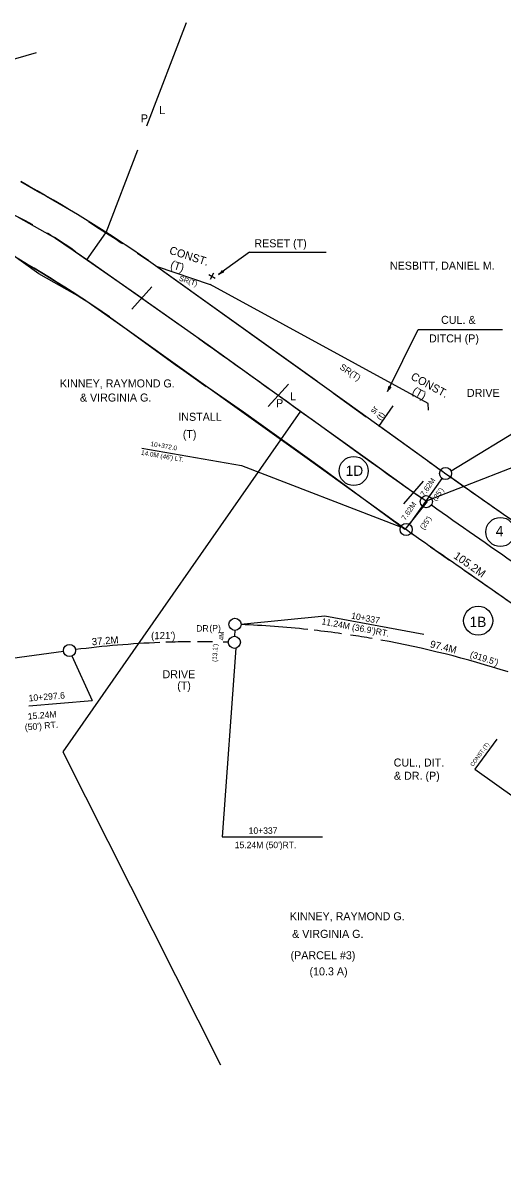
# Model space of a CAD drawing. Extents: x 624 to 1448, y 1599 to 1865.
# Drawn here: x 1147.3 to 1254.2, y 1600.9 to 1857.1 of the extents above; entities that cross this region are included whole.
import ezdxf

# ---------------------------------------------------------------- set-up
doc = ezdxf.new("R2010")
doc.units = 0
for name, color, linetype in [('C_I', 7, 'Continuous'), ('C_TIC', 7, 'Continuous'), ('CPSM', 7, 'Continuous'), ('L_A', 7, 'Continuous'), ('L_C', 7, 'Continuous'), ('L_I', 7, 'Continuous'), ('Level 16', 7, 'Continuous'), ('Level 30', 7, 'Continuous'), ('Level 60', 7, 'Continuous'), ('ODIML_P', 7, 'Continuous')]:
    doc.layers.add(name, color=color, linetype=linetype)

msp = doc.modelspace()

# ---------------------------------------------------------------- linework, layer by layer
at = {"layer": 'C_I'}
for p, q in [((1143.46, 1848.56), (1150.35, 1850.6)), ((1197.77, 1806.11), (1190.88, 1801.09)), ((1197.77, 1806.11), (1214.81, 1806.11)), ((1188.67, 1801.12), (1190.07, 1800.3)), ((1189.75, 1801.38), (1188.99, 1800.01)), ((1228.5, 1775.03), (1235.33, 1788.84)), ((1235.33, 1788.84), (1254.06, 1788.84)), ((1226.51, 1767.27), (1229.73, 1771.85)), ((1252.79, 1697.62), (1247.89, 1690.87)), ((1247.89, 1690.87), (1257.19, 1684.28))]:
    msp.add_line(p, q, dxfattribs=at)
at = {"layer": 'C_TIC'}
for p, q in [((1194.47, 1721.9), (1194.42, 1720.55)), ((1119.66, 1712.21), (1156.34, 1717.18))]:
    msp.add_line(p, q, dxfattribs=at)
for centre, radius, start, end in [((1186.82, 1499.54), 223.76, 83.8659, 87.6946), ((1186.82, 1499.54), 223.76, 81.9273, 83.5023), ((1186.82, 1499.54), 219.76, 90.5767, 91.9984), ((1186.82, 1499.54), 219.76, 89.2914, 90.1765), ((1185.68, 1499.56), 219.76, 88.0891, 88.3832), ((1186.82, 1499.54), 223.76, 80.1531, 81.412), ((1186.82, 1499.54), 223.76, 72.1716, 79.6486), ((1186.82, 1499.54), 219.76, 92.3655, 97.2601)]:
    msp.add_arc(centre, radius, start, end, dxfattribs=at)
at = {"layer": 'CPSM'}
msp.add_line((1342.48, 1791.88), (1237.06, 1750.6), dxfattribs=at)
at = {"layer": 'L_A'}
msp.add_lwpolyline([(1146.28, 1813.9), (1154.59, 1809.17), (1162.17, 1803.99), (1188.52, 1785.46), (1210.43, 1769.73), (1224.02, 1759.93), (1233.89, 1752.85), (1237.31, 1750.56), (1232.37, 1744.32), (1213.97, 1757.79), (1196.41, 1770.43), (1181.23, 1780.96), (1170.26, 1788.9), (1160.59, 1795.77), (1150.85, 1801.23), (1144.54, 1805.75)], dxfattribs=at)
at = {"layer": 'L_C'}
for p, q in [((1242.65, 1757.37), (1310.72, 1798.99)), ((1173.78, 1762.38), (1195.97, 1758.57)), ((1195.97, 1758.57), (1231.37, 1744.86))]:
    msp.add_line(p, q, dxfattribs=at)
for centre in [(1220.95, 1757.33), (1253.6, 1743.74), (1248.67, 1723.98)]:
    msp.add_circle(centre, 3.24, dxfattribs=at)
at = {"layer": 'L_I'}
for p, q in [((1183.62, 1857.14), (1174.84, 1834.12)), ((1172.83, 1828.83), (1165.8, 1810.41)), ((1161.54, 1804.41), (1165.8, 1810.41)), ((1159.03, 1806.19), (1174.09, 1795.65)), ((1173.78, 1795.87), (1182.3, 1789.8)), ((1209.12, 1770.66), (1156.17, 1694.8)), ((1233.4, 1745.4), (1240.63, 1755.67)), ((1195.84, 1723.22), (1214.52, 1725.06)), ((1214.52, 1725.06), (1236.55, 1720.96)), ((1194.73, 1717.88), (1191.7, 1675.82)), ((1158.23, 1716.16), (1162.72, 1706.21)), ((1148.65, 1705.04), (1162.72, 1706.21)), ((1156.17, 1694.8), (1191.31, 1625.06)), ((1191.7, 1675.82), (1213.99, 1675.82))]:
    msp.add_line(p, q, dxfattribs=at)
for centre in [(1241.41, 1756.77), (1237.12, 1750.5), (1232.62, 1744.3), (1194.52, 1723.17), (1194.38, 1719.17), (1157.66, 1717.35)]:
    msp.add_circle(centre, 1.35, dxfattribs=at)
for start, end in [(61.0375, 77.7037), (54.5772, 58.8831)]:
    msp.add_arc((1101.07, 1724.7), 100, start, end, dxfattribs=at)
for points in [[(1186.37, 1786.9), (1204.16, 1774.21), (1234.31, 1752.55), (1236.02, 1751.34)], [(1238.24, 1749.77), (1257.42, 1736.33), (1273.09, 1725.39)]]:
    msp.add_spline(points, degree=3, dxfattribs=at)
at = {"layer": 'Level 16'}
for p, q in [((1191.71, 1801.86), (1191.6, 1801.68)), ((1191.87, 1801.64), (1191.66, 1801.6)), ((1191.75, 1802), (1191.81, 1801.76)), ((1192.02, 1801.63), (1191.8, 1801.76)), ((1228.83, 1776.24), (1228.99, 1776.05)), ((1228.87, 1776.09), (1228.86, 1775.88)), ((1229.1, 1775.98), (1228.94, 1775.84)), ((1229.24, 1776.04), (1228.99, 1776.05))]:
    msp.add_line(p, q, dxfattribs=at)
for centre, start, end in [((1188.87, 1803.86), 306.0701, 327.2934), ((1192.9, 1798.33), 104.8731, 126.0963), ((1225.42, 1776.5), 334.3662, 355.5894), ((1231.58, 1773.55), 133.1691, 154.3924)]:
    msp.add_arc(centre, 3.42, start, end, dxfattribs=at)
at = {"layer": 'Level 30'}
for p, q in [((1237.55, 1772.39), (1188.98, 1798.88)), ((1237.64, 1770.88), (1237.55, 1772.39))]:
    msp.add_line(p, q, dxfattribs=at)
msp.add_lwpolyline([(1176.99, 1802.96), (1188.98, 1798.88)], dxfattribs=at)
at = {"layer": 'Level 60'}
for p, q in [((1171.57, 1793.36), (1175.98, 1798.38)), ((1201.89, 1771.73), (1206.43, 1776.7)), ((1232.09, 1750.02), (1236.52, 1755.09))]:
    msp.add_line(p, q, dxfattribs=at)
at = {"layer": 'ODIML_P'}
for p, q in [((1219.45, 1772.59), (1237.38, 1759.66)), ((1210.59, 1760.2), (1228.64, 1747.17))]:
    msp.add_line(p, q, dxfattribs=at)
for points in [[(1146.82, 1821.82), (1148.25, 1821.02), (1149.68, 1820.22), (1151.1, 1819.41), (1152.52, 1818.59), (1153.94, 1817.77), (1155.35, 1816.94), (1156.76, 1816.1), (1158.01, 1815.36)], [(1161.9, 1812.88), (1162.32, 1812.62), (1163.7, 1811.75), (1165.09, 1810.87), (1166.47, 1809.98), (1167.84, 1809.09), (1169.21, 1808.19), (1169.47, 1808.03)], [(1146.41, 1804.52), (1147.79, 1803.71), (1149.16, 1802.89), (1150.54, 1802.06), (1151.9, 1801.23), (1153.27, 1800.39), (1154.63, 1799.54), (1155.98, 1798.69), (1157.33, 1797.83), (1158.68, 1796.96), (1160.02, 1796.09), (1161.36, 1795.21), (1162.69, 1794.32), (1164.02, 1793.43), (1165.35, 1792.53), (1166.59, 1791.67), (1166.38, 1791.82), (1177.08, 1784.17)], [(1172.8, 1805.88), (1173.34, 1805.52), (1174.69, 1804.59), (1175.24, 1804.22), (1175.24, 1804.22), (1212.71, 1777.41)], [(1175.24, 1804.22), (1219.45, 1772.59)], [(1166.38, 1791.82), (1210.59, 1760.2)], [(1180.79, 1781.42), (1188.1, 1776.19)], [(1191.37, 1773.94), (1210.59, 1760.2), (1228.64, 1747.17), (1228.65, 1747.17), (1229.73, 1746.39), (1230.55, 1745.8), (1231.53, 1745.1)], [(1216.42, 1774.66), (1219.41, 1772.53), (1223.72, 1769.42)], [(1226.98, 1767.16), (1237.38, 1759.66), (1237.38, 1759.65), (1238.49, 1758.85), (1240.31, 1757.55)], [(1242.51, 1756), (1248.06, 1752.11), (1254.3, 1747.74), (1260.54, 1743.37), (1266.78, 1739), (1269.31, 1737.23)], [(1233.73, 1743.53), (1235.14, 1742.53)], [(1238.02, 1740.45), (1239.24, 1739.6), (1242.28, 1737.47)], [(1245.57, 1735.26), (1251.8, 1730.9), (1258.05, 1726.53), (1264.29, 1722.16), (1270.53, 1717.79), (1271.9, 1716.83), (1273.28, 1715.86), (1278.14, 1712.45), (1283.01, 1709.04), (1285.73, 1707.14)]]:
    msp.add_lwpolyline(points, dxfattribs=at)
for radius in [335.89, 320.65]:
    msp.add_arc((984.41, 1527.8), radius, 55.3797, 61.0858, dxfattribs=at)
for points in [[(1237.38, 1759.65), (1241.82, 1756.48), (1254.3, 1747.74), (1266.78, 1739), (1279.27, 1730.26), (1282.01, 1728.34), (1291.75, 1721.52), (1304.23, 1712.78), (1316.72, 1704.04), (1329.16, 1695.32), (1341.82, 1686.83), (1354.38, 1678.04), (1366.69, 1669.05), (1379.22, 1660.23), (1391.46, 1650.9), (1403.62, 1641.59), (1415.8, 1632.22), (1427.84, 1622.54), (1439.44, 1612.4)], [(1228.65, 1747.17), (1233, 1744.06), (1245.56, 1735.27), (1258.05, 1726.53), (1270.53, 1717.79), (1273.28, 1715.86), (1283.01, 1709.04), (1295.5, 1700.3), (1307.98, 1691.56), (1320.55, 1682.76), (1333.21, 1674.27), (1345.52, 1665.65), (1357.82, 1656.67), (1370.21, 1647.94), (1382.21, 1638.79), (1394.35, 1629.5), (1406.38, 1620.25), (1418.05, 1610.87), (1429.41, 1600.93)]]:
    msp.add_spline(points, degree=3, dxfattribs=at)

# ---------------------------------------------------------------- texts
at = {"layer": 'C_I'}
for s, height, p in [('RESET (T)', 1.783, (1198.84, 1807.17)), ('CUL. &', 1.783, (1240.41, 1790.11)), ('DITCH (P)', 1.783, (1237.71, 1785.98)), ('DRIVE', 1.783, (1246.16, 1773.84)), ('INSTALL', 1.783, (1181.9, 1768.51)), ('(T)', 1.783, (1182.9, 1764.65)), ('DR', 1.426, (1185.9, 1721.56)), ('(P)', 1.426, (1188.83, 1721.63)), ('DRIVE', 1.783, (1178.38, 1711.16)), ('(T)', 1.783, (1181.65, 1708.63)), ('CUL., DIT. ', 1.783, (1229.84, 1691.49)), ('& DR. (P)', 1.783, (1229.91, 1688.55))]:
    msp.add_text(s, height=height, dxfattribs=at).set_placement(p)
for s, height, rotation, p in [('CONST.', 1.783, 342.1843, (1179.75, 1805.76)), ('(T)', 1.783, 342.1843, (1179.98, 1802.61)), ('SR(T)', 1.141, 341.1277, (1181.97, 1799.8)), ('SR(T)', 1.426, 326.5512, (1217.7, 1780.14)), ('CONST.', 1.783, 331.5584, (1233.49, 1777.84)), ('(T)', 1.783, 331.5584, (1233.81, 1774.63)), ('sr', 1.4, 54.8664, (1225.59, 1769.95)), ('(t)', 1.4, 54.8664, (1227.01, 1768.44)), ('7.62M', 1.17, 55.1084, (1236.64, 1751.58)), ("(25')", 1.17, 55.1084, (1239.28, 1750.51)), ('7.62M', 1.17, 55.1084, (1232.42, 1746.24)), ("(25')", 1.17, 55.1084, (1236.53, 1744.15)), ('105.2M', 1.783, 324.915, (1243.02, 1738.05)), ('37.2M', 1.605, 4.5423, (1162.7, 1718.49)), ("(121')", 1.605, 0.5423, (1175.84, 1719.85)), ('4M', 1.04, 87.3955, (1191.99, 1719.57)), ('97.4M', 1.605, 346.3199, (1237.84, 1718.06)), ("(13.1')", 1.04, 87.3955, (1190.49, 1714.78)), ("(319.5')", 1.444, 342.3199, (1246.73, 1715.89)), ('CONST.(T)', 0.891, 54.0302, (1247.53, 1691.41))]:
    msp.add_text(s, height=height, rotation=rotation, dxfattribs=at).set_placement(p)
at = {"layer": 'L_A'}
for s, p in [('NESBITT, DANIEL M.', (1229.02, 1802.19)), ('KINNEY, RAYMOND G.', (1155.54, 1775.95)), ('& VIRGINIA G.', (1159.99, 1772.8)), ('KINNEY, RAYMOND G.', (1206.73, 1657.24)), ('& VIRGINIA G.', (1207.23, 1653.32)), ('(PARCEL #3)', (1206.89, 1648.55)), ('(10.3 A)', (1211.11, 1644.96))]:
    msp.add_text(s, height=1.783, dxfattribs=at).set_placement(p)
at = {"layer": 'L_C'}
for s, height, rotation, p in [('10+372.0', 1.027, 350.24, (1175.66, 1762.91)), ("14.0M (46') LT.", 1.0398, 350.24, (1173.53, 1760.95)), ("11.24M (36.9')RT.", 1.426, 349.4603, (1213.71, 1723.18)), ('10+337', 1.426, 349.4603, (1220.31, 1724.45)), ('10+297.6', 1.444, 4.748, (1148.62, 1705.99)), ('15.24M', 1.444, 4.748, (1148.44, 1701.94)), ("(50') RT.", 1.444, 4.748, (1147.78, 1699.52))]:
    msp.add_text(s, height=height, rotation=rotation, dxfattribs=at).set_placement(p)
for s, height, p in [('1D', 2.286, (1219.16, 1756.25)), ('4', 2.29, (1252.58, 1742.81)), ('1B', 2.286, (1246.74, 1722.58)), ('10+337', 1.426, (1197.56, 1676.5)), ("15.24M (50')RT.", 1.426, (1194.47, 1673.3))]:
    msp.add_text(s, height=height, dxfattribs=at).set_placement(p)
at = {"layer": 'L_I'}
for s, p in [('L', (1177.66, 1836.85)), ('P', (1173.56, 1835)), ('P', (1203.67, 1771.55)), ('L', (1206.8, 1773.1))]:
    msp.add_text(s, height=1.78, dxfattribs=at).set_placement(p)

doc.saveas('drawing.dxf')
